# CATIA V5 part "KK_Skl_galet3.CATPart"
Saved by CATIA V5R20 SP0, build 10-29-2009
Part number: Skl_galet3
Publications: "Axe_pivot_galet3", "Plan.Ref5", "Point.2", "Plan_Ref1"
Bounding box of the stored display mesh (mm): x -7.5 to 32.5, y 232 to 232, z 15 to 15
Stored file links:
  G:\Khaled_CFAO_2011\ST2M\ST2M_GR2\aandujar\Khaled\CAD_thinkMOTION\KK_Skl_galet3.CATPart
  G:\Khaled_CFAO_2011\ST2M\ST2M_GR2\aandujar\Khaled\CAD_thinkMOTION\KK_Skl_scie_mecanique.CATProduct
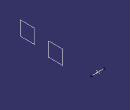
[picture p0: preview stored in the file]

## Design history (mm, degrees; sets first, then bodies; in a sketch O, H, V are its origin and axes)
WSupportSet1: ActiveGrid {3dwsupport RefPoint {point stored without definition}, 3DWOS ({wsupport Support xy-plane, RefPoint {3dwsupport}, GridIn {cartgrid Value 100, Stepbid1 0, Value 100, Stepbid2 0, Direction (1, 0, 0)}, GeometricData ({line type PtDir, Direction (1, 0, 0), Support xy-plane}; {line type PtDir, Direction (0, 1, 0), Support yz-plane})}; {wsupport Support yz-plane, RefPoint {3dwsupport}, GridIn {cartgrid Value 100, Stepbid1 0, Value 100, Stepbid2 0, Direction (0, 1, 0)}, GeometricData ({line type PtDir, Direction (0, 1, 0), Support yz-plane}; {line type PtDir, Direction (0, 0, 1), Support zx-plane})}; {wsupport Support zx-plane, RefPoint {3dwsupport}, GridIn {cartgrid Value 100, Stepbid1 0, Value 100, Stepbid2 0, Direction (0, 0, 1)}, GeometricData ({line type PtDir, Direction (0, 0, 1), Support zx-plane}; {line type PtDir, Direction (1, 0, 0), Support xy-plane})}), GeometricData ({line type PtDir, RefPoint {point stored without definition}, Direction (1, 0, 0), Support xy-plane}; {line type PtDir, RefPoint {point stored without definition}, Direction (0, 1, 0), Support yz-plane}; {line type PtDir, RefPoint {point stored without definition}, Direction (0, 0, 1), Support zx-plane})}
Set1
  Line1 "Axe_pivot_galet3": type Normal, RefPoint Point1, RefSkin Plane2, Start -20, End 20
Set2
  Plane1 "Plan.Ref5": linked copy from another document
  Point1: linked copy from another document
  Plane2 "Plan_Ref1": linked copy from another document
Body1 (main body)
